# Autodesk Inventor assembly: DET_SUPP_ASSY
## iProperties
Shininess: 64.0
Length Units: 11272
Angle Units: 11279
Time Units: 11290
Mass Units: 11286
Length Display Precision: 3
Angle Display Precision: 2
Compacted: True
Part Number: DET_SUPP_ASSY
Document SubType Name: Assembly
Created: 2004-08
Designer: John Blackburn
Manufacturer: Standard
Standards Organization: Custom
Density: 0.0
Volumn: 0.0
Area: 0.0
PropertySet Name: Model Information
Control State: 0
Master: False
Checked Out: False
Author: John Blackburn
